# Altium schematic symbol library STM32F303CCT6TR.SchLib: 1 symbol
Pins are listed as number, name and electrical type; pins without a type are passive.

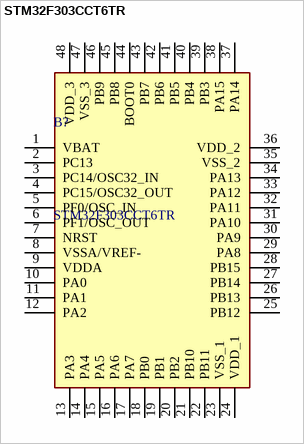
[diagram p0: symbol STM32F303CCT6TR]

## STM32F303CCT6TR
designator B?
ARM Microcontrollers - MCU Mainstream Mixed signals MCUs ARM Cortex-M4 core with DSP and FPU, 256 Kbytes Flash, 72 MHz CPU, MPU, CCM, 12-bit ADC 5 MSPS, PGA, comparators; Manufacturer_Name: STMicroelectronics; Geometry.Height: 1.6mm
footprint QFP50P900X900X160-48N
pins: 1 VBAT, 2 PC13, 3 PC14/OSC32_IN, 4 PC15/OSC32_OUT, 5 PF0/OSC_IN, 6 PF1/OSC_OUT, 7 NRST, 8 VSSA/VREF-, 9 VDDA, 10 PA0, 11 PA1, 12 PA2, 13 PA3, 14 PA4, 15 PA5, 16 PA6, 17 PA7, 18 PB0, 19 PB1, 20 PB2, 21 PB10, 22 PB11, 23 VSS_1, 24 VDD_1, 25 PB12, 26 PB13, 27 PB14, 28 PB15, 29 PA8, 30 PA9, 31 PA10, 32 PA11, 33 PA12, 34 PA13, 35 VSS_2, 36 VDD_2, 37 PA14, 38 PA15, 39 PB3, 40 PB4, 41 PB5, 42 PB6, 43 PB7, 44 BOOT0, 45 PB8, 46 PB9, 47 VSS_3, 48 VDD_3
